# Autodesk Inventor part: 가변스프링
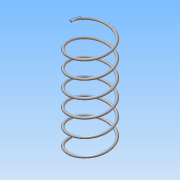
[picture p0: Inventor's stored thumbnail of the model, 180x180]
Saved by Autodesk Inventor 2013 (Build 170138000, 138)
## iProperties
Created: 2016-11
Part Number: 가변스프링
Material: 알루미늄 6061
Document SubType Name: Modeling
Designer: Administrator
Density: 2.71 g/cm^3
Mass: 5.11241 g
Surface Area: 38.0232 cm^2
Volume: 1.8865 cm^3
Author: Administrator
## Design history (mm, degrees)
sketch "스케치1"
  geometry: L1 (0, 0)-(16, 0); L2 (16, 0)-(16, 84.368); L3 (16, 84.368)-(0, 84.368); L4 (0, 84.368)-(0, 0); C1 r 1 at (16, 0)
  constraints: 8 end point, 2 parallel, 1 centre point, 1 coincident, 1 horizontal, 1 perpendicular
  dimensions: "d0" = 84.36759 distance of L1.end L2.end (derived); "d2" = 16 distance of L2.end L3.end; "d3" = 2 diameter of C1
feature "코일1" sketch "스케치1" pitch "d4" = 10; turns "d6" = 6; dims "d5" = 84.36759 (= d0), "d7" = 0, angle "d8" = 90 deg, angle "d9" = 90 deg, "d10" = 0, "d11" = 0
sketch "스케치2"
  geometry: L1 (-15.54, 0)-(52.453, 0); L2 (52.453, 0)-(52.453, -84.368); L3 (52.453, -84.368)-(-15.54, -84.368); L4 (-15.54, -84.368)-(-15.54, 0); 5 further points
  constraints: 8 end point, 2 horizontal alignment, 2 parallel, 2 point on line, 1 horizontal, 1 perpendicular
extrude "돌출1" sketch "스케치2" stored distance "d12" = 0; taper "d13" = 0 deg
node "솔리드1"
